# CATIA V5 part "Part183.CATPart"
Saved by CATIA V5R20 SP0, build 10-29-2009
Part number: 9FA 126712
Revision: ANY
Definition: UNKNOWN
Nomenclature: 9FA 126712
Source: Unknown
Bounding box of the stored display mesh (mm): x -5.85 to 5.85, y -10 to 10, z -6 to 6
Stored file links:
  C:\Users\Utente\Desktop\IO LAVORO\3D X SITO CF\CUMSA\3D files FA\FA 126712-20\Part183.CATPart

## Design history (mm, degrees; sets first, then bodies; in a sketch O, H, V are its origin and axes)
Body1 "Cortar-Extruir5" (main body)
  Solid1: solid without history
